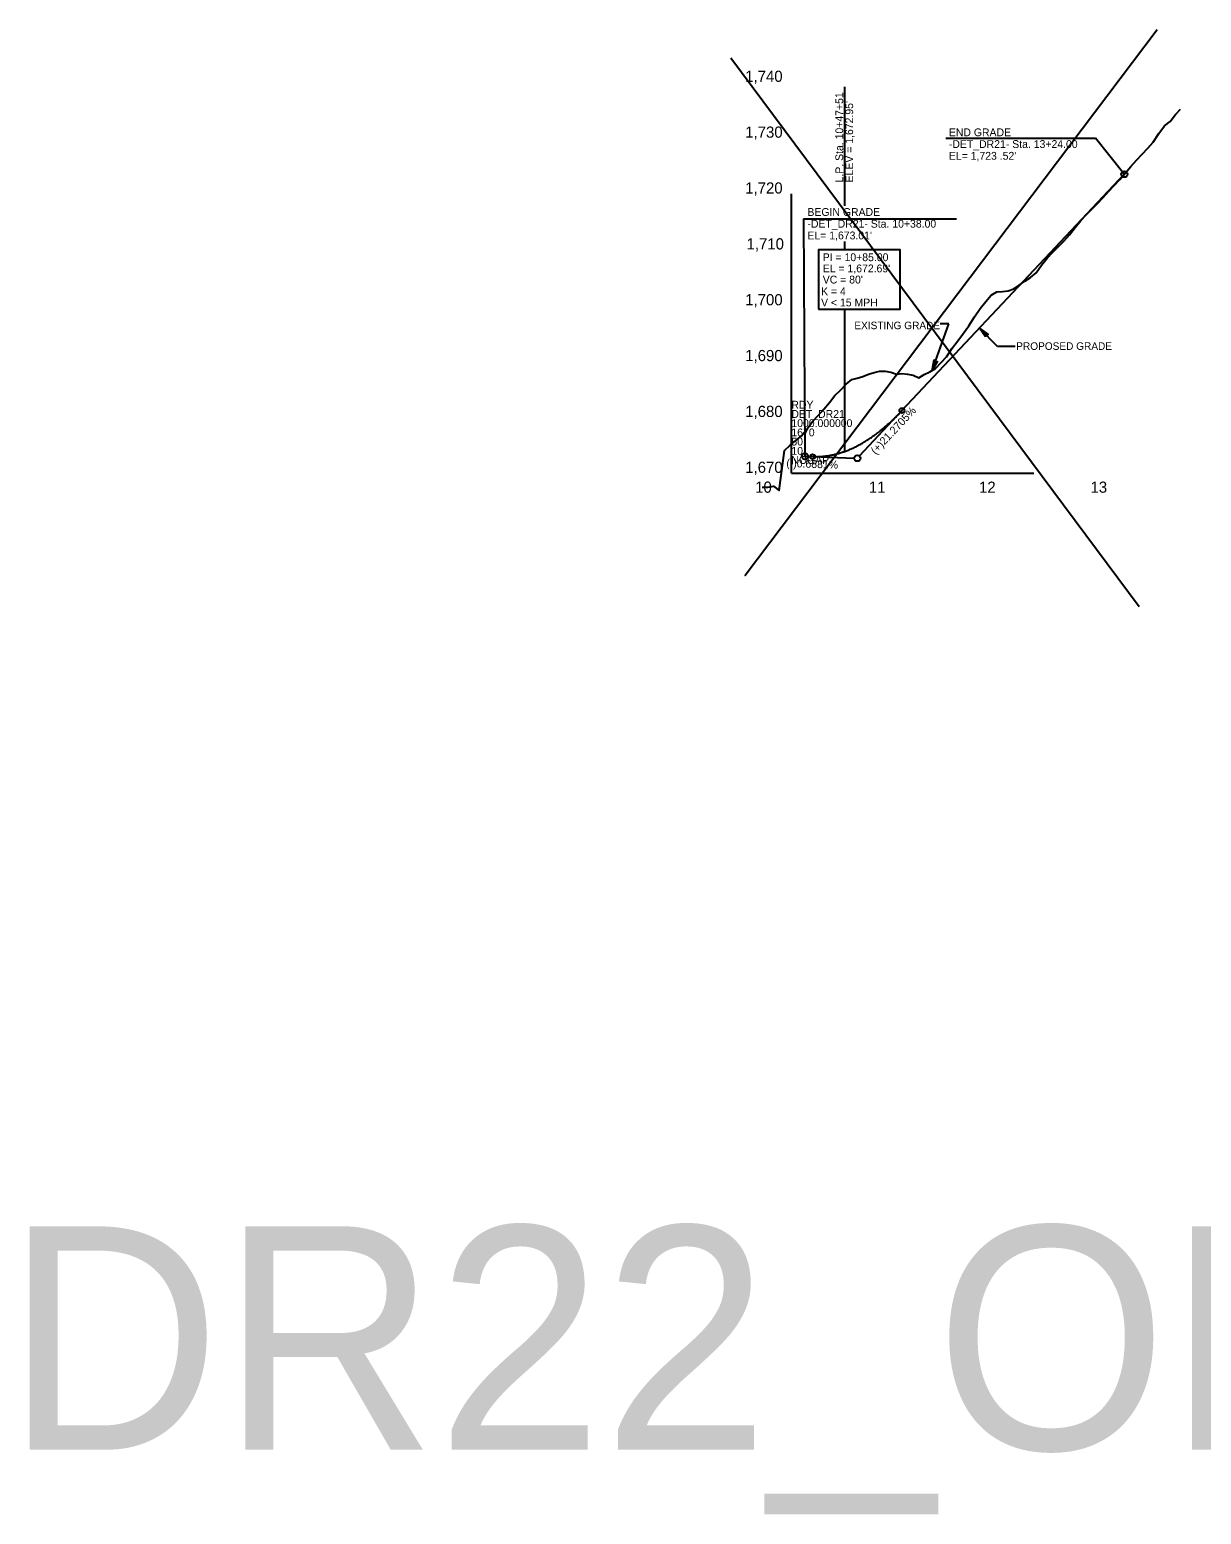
# Model space of a CAD drawing. Extents: x 498575 to 532350, y 405181 to 484585.
# Drawn here: x 529982 to 531031, y 426983 to 428312 of the extents above; entities that cross this region are included whole.
import ezdxf

# ---------------------------------------------------------------- set-up
doc = ezdxf.new("R2010")
doc.units = 0
for name, color, linetype in [('Exist Profile Cell', 7, 'Continuous'), ('Exist Vertical Profile Ground Line', 7, 'Continuous'), ('Exist Vertical Profile Horizontal Axis Label Major', 7, 'Continuous'), ('Exist Vertical Profile Vertical Axis Label', 7, 'Continuous'), ('Prop Grid Mask', 7, 'Continuous'), ('Prop PFL Text', 7, 'Continuous'), ('Prop Vertical Profile Curve Label', 7, 'Continuous'), ('Prop Vertical Profile Grade', 7, 'Continuous'), ('Prop Vertical Profile Grade Label', 7, 'Continuous'), ('Prop Vertical Profile Strip Grade', 7, 'Continuous'), ('Prop VPI Label', 7, 'Continuous'), ('Scratch_Level_5', 7, 'Continuous'), ('Scratch_Level_7', 7, 'Continuous'), ('Typical Terminator CELL', 7, 'Continuous')]:
    doc.layers.add(name, color=color, linetype=linetype)

# ---------------------------------------------------------------- blocks, each defined once
blk = doc.blocks.new('TERMINATOR')
at = {"layer": 'Typical Terminator CELL'}
blk.add_lwpolyline([(-0.469, 0.081), (0, 0), (-0.471, -0.083), (-0.411, 0)], close=True, dxfattribs=at)

msp = doc.modelspace()

# ---------------------------------------------------------------- linework, layer by layer
at = {"layer": 'Exist Profile Cell'}
for q in [(530664.1, 428164.7), (530881.2, 427914.7), (530664.1, 427914.7)]:
    msp.add_line((530664.1, 427914.7), q, dxfattribs=at)
at = {"layer": 'Exist Vertical Profile Ground Line'}
msp.add_lwpolyline([(530638.1, 427902.1), (530643.1, 427902.3), (530648.1, 427903.1), (530653.1, 427899.3), (530658.1, 427934.9), (530663.1, 427939.8), (530668.1, 427943.9), (530673.1, 427948), (530678.1, 427954.4), (530683.1, 427960.9), (530688.1, 427966.2), (530693.1, 427971.9), (530698.1, 427977.9), (530703.1, 427984.3), (530708.1, 427989), (530713.1, 427994.4), (530718.1, 427998.7), (530723.1, 427999.9), (530728.1, 428001.3), (530733.1, 428003.3), (530738.1, 428004.7), (530743.1, 428006), (530748.1, 428006), (530753.1, 428005), (530758.1, 428003.4), (530763.1, 428004), (530768.1, 428003.3), (530773.1, 428002.5), (530778.1, 428000.1), (530783.1, 428002.9), (530788.1, 428005.5), (530793.1, 428008.4), (530798.1, 428013.8), (530803.1, 428018.8), (530808.1, 428026.5), (530813.1, 428033.2), (530818.1, 428040), (530823.1, 428046.7), (530828.1, 428054.7), (530833.1, 428062), (530838.1, 428068.5), (530843.1, 428074.2), (530848.1, 428076.9), (530853.1, 428077.4), (530858.1, 428078), (530863.1, 428079.8), (530868.1, 428082.9), (530873.1, 428086.6), (530878.1, 428090), (530883.1, 428094.1), (530888.1, 428100.8), (530893.1, 428107.3), (530898.1, 428112.5), (530903.1, 428117.5), (530908.1, 428122.5), (530913.1, 428128), (530918.1, 428134.5), (530923.1, 428140.8), (530928.1, 428145.9), (530933.1, 428151.1), (530938.1, 428156.2), (530943.1, 428161.4), (530948.1, 428166.8), (530953.1, 428172.1), (530958.1, 428177.5), (530963.1, 428183.5), (530968.1, 428189.3), (530973.1, 428194.9), (530978.1, 428200.3), (530983.1, 428205.7), (530988.1, 428211.1), (530993.1, 428218.7), (530998.1, 428225.5), (531003.1, 428229.6), (531008.1, 428235.8), (531012.3, 428240.6)], dxfattribs=at)
at = {"layer": 'Prop Grid Mask'}
msp.add_lwpolyline([(530688.5, 428061.4), (530761.5, 428061.4), (530761.5, 428114.5), (530688.5, 428114.5)], close=True, dxfattribs=at)
at = {"layer": 'Prop PFL Text'}
for p, q in [((530790.2, 428006.7), (530805.2, 428048.3)), ((530805.2, 428048.3), (530797.2, 428048.3)), ((530848.5, 428028.2), (530832.4, 428044.4)), ((530864.5, 428028.2), (530848.5, 428028.2))]:
    msp.add_line(p, q, dxfattribs=at)
at = {"layer": 'Prop Vertical Profile Curve Label'}
for centre in [(530763.1, 427970.7), (530683.1, 427929.5)]:
    msp.add_circle(centre, 2.25, dxfattribs=at)
at = {"layer": 'Prop Vertical Profile Grade'}
for p, q in [((530763.1, 427970.7), (530962.1, 428182.3)), ((530676.2, 427929.8), (530683.1, 427929.5))]:
    msp.add_line(p, q, dxfattribs=at)
msp.add_spline([(530683.1, 427929.5), (530684.7, 427929.5), (530686.3, 427929.5), (530687.9, 427929.5), (530689.5, 427929.6), (530691.1, 427929.7), (530692.7, 427929.8), (530694.3, 427930), (530695.9, 427930.2), (530697.5, 427930.4), (530699.1, 427930.7), (530700.7, 427931), (530702.3, 427931.4), (530703.9, 427931.8), (530705.5, 427932.2), (530707.1, 427932.6), (530708.7, 427933.1), (530710.3, 427933.7), (530711.9, 427934.2), (530713.5, 427934.8), (530715.1, 427935.4), (530716.7, 427936.1), (530718.3, 427936.8), (530719.9, 427937.5), (530721.5, 427938.3), (530723.1, 427939.1), (530724.7, 427940), (530726.3, 427940.8), (530727.9, 427941.7), (530729.5, 427942.7), (530731.1, 427943.7), (530732.7, 427944.7), (530734.3, 427945.7), (530735.9, 427946.8), (530737.5, 427948), (530739.1, 427949.1), (530740.7, 427950.3), (530742.3, 427951.5), (530743.9, 427952.8), (530745.5, 427954.1), (530747.1, 427955.4), (530748.7, 427956.8), (530750.3, 427958.2), (530751.9, 427959.6), (530753.5, 427961.1), (530755.1, 427962.6), (530756.7, 427964.2), (530758.3, 427965.7), (530759.9, 427967.3), (530761.5, 427969), (530763.1, 427970.7)], degree=3, dxfattribs=at)
at = {"layer": 'Prop Vertical Profile Strip Grade'}
for p, q in [((530711.6, 428260.4), (530711.6, 428154)), ((530711.6, 428122.2), (530711.6, 428114.5)), ((530711.6, 428061.4), (530711.6, 427934.1))]:
    msp.add_line(p, q, dxfattribs=at)
at = {"layer": 'Prop VPI Label'}
for p, q in [((530802.3, 428214.6), (530936.3, 428214.6)), ((530962.1, 428182.3), (530936.3, 428214.6)), ((530674.9, 428142.5), (530676.2, 427929.8)), ((530674.9, 428142.5), (530811.9, 428142.5)), ((530763.1, 427970.7), (530725, 427930.1)), ((530683.1, 427929.5), (530720.3, 427928.2))]:
    msp.add_line(p, q, dxfattribs=at)
for centre in [(530962.1, 428182.3), (530676.2, 427929.8), (530723.1, 427928.1)]:
    msp.add_circle(centre, 2.75, dxfattribs=at)
at = {"layer": 'Scratch_Level_5'}
msp.add_line((530609.9, 428286.6), (530975.5, 427795.5), dxfattribs=at)
msp.add_lwpolyline([(530991.7, 428311.7), (530622.8, 427823), (530622.8, 427823)], dxfattribs=at)

# ---------------------------------------------------------------- block references
at = {"layer": 'Prop PFL Text'}
for p, xscale, yscale, rotation in [((530832.4, 428044.4), 19.999999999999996, 19.999999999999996, 135.07485040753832), ((530790.2, 428006.7), 20, 20.000000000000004, -109.86448305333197)]:
    msp.add_blockref('TERMINATOR', p, dxfattribs=dict(at, xscale=xscale, yscale=yscale, rotation=rotation))

# ---------------------------------------------------------------- texts
at = {"layer": 'Exist Profile Cell'}
for s, p in [('RDY', (530664.1, 427972.5)), ('DET_DR21', (530664.1, 427964.2)), ('1000.000000', (530664.1, 427956)), ('1670', (530664.1, 427947.7)), ('50', (530664.1, 427939.5)), ('10', (530664.1, 427931.2)), ('NOGAP', (530664.1, 427923))]:
    msp.add_text(s, height=7, dxfattribs=at).set_placement(p)
at = {"layer": 'Exist Vertical Profile Horizontal Axis Label Major'}
for s, p in [('10', (530631.7, 427897.2)), ('11', (530733.5, 427897.2)), ('12', (530832.1, 427897.2)), ('13', (530931.9, 427897.2))]:
    msp.add_text(s, height=10, dxfattribs=at).set_placement(p)
at = {"layer": 'Exist Vertical Profile Vertical Axis Label'}
for s, p in [('1,740', (530622.8, 428265)), ('1,730', (530622.8, 428215)), ('1,720', (530622.8, 428165)), ('1,710', (530624, 428115)), ('1,700', (530622.8, 428065)), ('1,690', (530622.8, 428015)), ('1,680', (530622.8, 427965)), ('1,670', (530622.8, 427915))]:
    msp.add_text(s, height=10, dxfattribs=at).set_placement(p)
at = {"layer": 'Prop PFL Text'}
for s, p in [('EXISTING GRADE', (530720.5, 428043.6)), ('PROPOSED GRADE', (530865.4, 428025.1))]:
    msp.add_text(s, height=6.75, dxfattribs=at).set_placement(p)
at = {"layer": 'Prop Vertical Profile Curve Label'}
for s, p in [('K = 4', (530690.7, 428074)), ("VC = 80'", (530692.2, 428084.5)), ('V < 15 MPH', (530690.7, 428064))]:
    msp.add_text(s, height=7, dxfattribs=at).set_placement(p)
at = {"layer": 'Prop Vertical Profile Grade Label'}
for s, rotation, p in [('(+)21.2705%', 46.7633, (530739.5, 427931)), ('(-)0.6881%', 358.0294, (530659.5, 427920.3))]:
    msp.add_text(s, height=7, rotation=rotation, dxfattribs=at).set_placement(p)
at = {"layer": 'Prop Vertical Profile Strip Grade'}
for s, p in [('L.P. Sta. 10+47+51', (530710.5, 428175)), ("ELEV = 1,672.95'", (530719.4, 428175))]:
    msp.add_text(s, height=7, rotation=90, dxfattribs=at).set_placement(p)
at = {"layer": 'Prop VPI Label'}
for s, p in [('END GRADE', (530805.1, 428216.3)), ('-DET_DR21- Sta. 13+24.00', (530805.1, 428205.8)), ("EL= 1,723 .52'", (530805.1, 428195.3)), ('BEGIN GRADE', (530678.5, 428145)), ('-DET_DR21- Sta. 10+38.00', (530678.5, 428134.5)), ("EL= 1,673.01'", (530678.5, 428124)), ('PI = 10+85.00', (530692.2, 428104.5)), ("EL = 1,672.69'", (530692.2, 428094.5))]:
    msp.add_text(s, height=7, dxfattribs=at).set_placement(p)
at = {"layer": 'Scratch_Level_7'}
msp.add_text('DR22_OLD', height=200, dxfattribs=at).set_placement((529960.3, 427040.6))

doc.saveas('drawing.dxf')
